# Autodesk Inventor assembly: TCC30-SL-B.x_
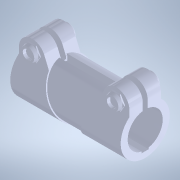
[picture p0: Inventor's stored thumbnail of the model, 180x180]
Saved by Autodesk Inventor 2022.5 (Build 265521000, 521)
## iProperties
Created: 2023-09
Part Number: TCC30-SL-B.x_
Document SubType Name: Assembly
Designer: ImaoCorp
Sending System: SOLIDWORKS 2021-2021301
MC: AMD64
MC_MODEL: Intel64 Family 6 Model 60 Stepping 3, GenuineIntel
OS: Windows_NT
FRU: Parasolid Version 32.1, build 255,  1- 1-2021
FORMAT: text
GUISE: transmit
KEY: TCC30-SL-B
FILE: TCC30-SL-B.x_t
DATE: Fri Sep 15 15:37:09 2023
Author: ImaoCorp
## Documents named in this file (6)
- X:\14_SW2022-Inv2022\00_全2023-1023新製品(TCC)まで\t\tcc30-sl-b\TCC30-SL-B.iam
- X:\14_SW2022-Inv2022\00_全2023-1023新製品(TCC)まで\t\tcc30-sl-b\TCC30-SL-B_01.ipt
- X:\14_SW2022-Inv2022\00_全2023-1023新製品(TCC)まで\t\tcc30-sl-b\TCC30-SL-B_02.ipt
- X:\14_SW2022-Inv2022\00_全2023-1023新製品(TCC)まで\t\tcc30-sl-b\TCC30-SL-B_03.ipt
- X:\14_SW2022-Inv2022\00_全2023-1023新製品(TCC)まで\t\tcc30-sl-b\TCC30-SL-B_04.ipt
- X:\14_SW2022-Inv2022\00_全2023-1023新製品(TCC)まで\t\tcc30-sl-b\TCC30-SL-B_05.ipt
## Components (5 placed, 5 different names)
1. TCC30-SL-B_01
2. TCC30-SL-B_02
3. TCC30-SL-B_03
4. TCC30-SL-B_04
5. TCC30-SL-B_05
